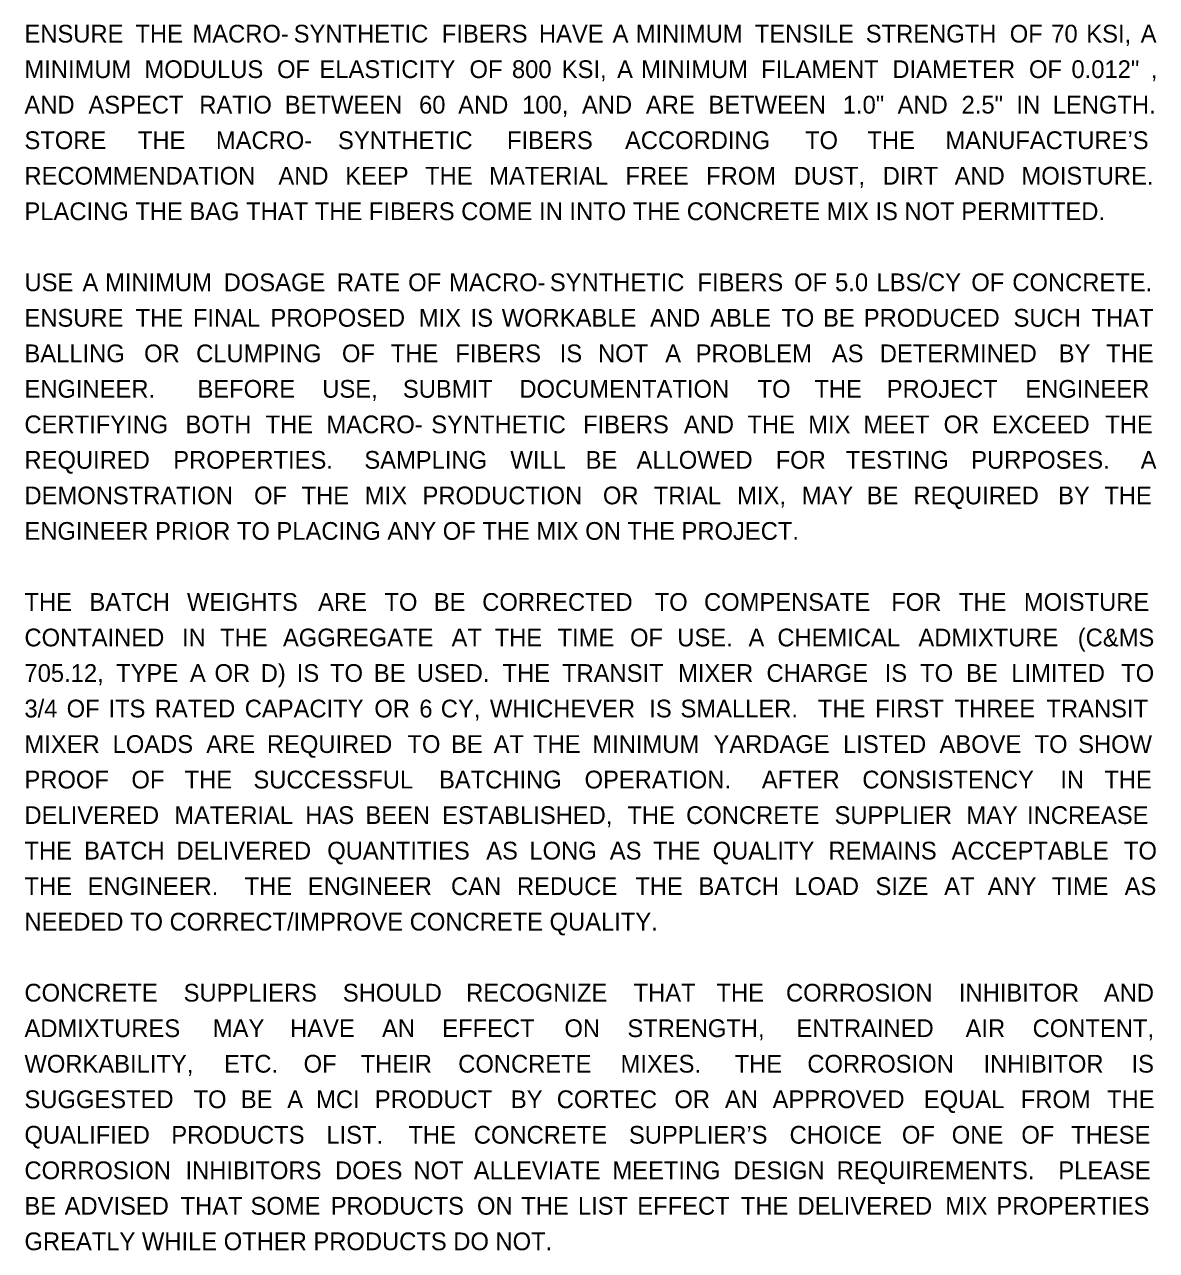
# Model space of a CAD drawing. Extents: x -19.8 to 34, y 0 to 22.
# Drawn here: x -19.82 to -10.9, y 1.96 to 11.62 of the extents above; entities that cross this region are included whole.
import ezdxf

# ---------------------------------------------------------------- set-up
doc = ezdxf.new("R2010")
doc.units = 0
doc.layers.add('SH_Text', color=7, linetype='Continuous')

msp = doc.modelspace()

# ---------------------------------------------------------------- texts
at = {"layer": 'SH_Text'}
for s, p in [('ENSURE ', (-19.8201, 11.48)), ('THE ', (-18.9457, 11.48)), ('MACRO-', (-18.4954, 11.48)), ('SYNTHETIC ', (-17.6975, 11.48)), ('FIBERS ', (-16.5298, 11.48)), ('HAVE ', (-15.7642, 11.48)), ('A ', (-15.1832, 11.48)), ('MINIMUM ', (-15.0009, 11.48)), ('TENSILE ', (-14.0619, 11.48)), ('STRENGTH ', (-13.1875, 11.48)), ('OF ', (-12.0525, 11.48)), ('70 ', (-11.7253, 11.48)), ('KSI, ', (-11.4489, 11.48)), ('A ', (-11.0202, 11.48)), ('MINIMUM ', (-19.8201, 11.2)), ('MODULUS ', (-18.8736, 11.2)), ('OF ', (-17.8289, 11.2)), ('ELASTICITY ', (-17.4943, 11.2)), ('OF ', (-16.3116, 11.2)), ('800 ', (-15.977, 11.2)), ('KSI, ', (-15.5843, 11.2)), ('A ', (-15.1482, 11.2)), ('MINIMUM ', (-14.9584, 11.2)), ('FILAMENT ', (-14.0119, 11.2)), ('DIAMETER ', (-12.9781, 11.2)), ('OF ', (-11.9008, 11.2)), ('0.012" ', (-11.5661, 11.2)), (', ', (-10.9409, 11.2)), ('AND ', (-19.8201, 10.92)), ('ASPECT ', (-19.3159, 10.92)), ('RATIO ', (-18.4421, 10.92)), ('BETWEEN ', (-17.7677, 10.92)), ('60 ', (-16.7092, 10.92)), ('AND ', (-16.4007, 10.92)), ('100, ', (-15.8965, 10.92)), ('AND ', (-15.4249, 10.92)), ('ARE ', (-14.9208, 10.92)), ('BETWEEN ', (-14.4274, 10.92)), ('1.0" ', (-13.3689, 10.92)), ('AND ', (-12.9366, 10.92)), ('2.5" ', (-12.4324, 10.92)), ('IN ', (-12.0001, 10.92)), ('LENGTH.  ', (-11.7134, 10.92)), ('STORE ', (-19.8201, 10.64)), ('THE ', (-18.926, 10.64)), ('MACRO-', (-18.311, 10.64)), ('SYNTHETIC ', (-17.3484, 10.64)), ('FIBERS ', (-16.016, 10.64)), ('ACCORDING ', (-15.0857, 10.64)), ('TO ', (-13.6665, 10.64)), ('THE ', (-13.1747, 10.64)), ('MANUFACTURE’S ', (-12.5597, 10.64)), ('RECOMMENDATION ', (-19.8201, 10.36)), ('AND ', (-17.8183, 10.36)), ('KEEP ', (-17.291, 10.36)), ('THE ', (-16.6619, 10.36)), ('MATERIAL ', (-16.1563, 10.36)), ('FREE ', (-15.0817, 10.36)), ('FROM ', (-14.4456, 10.36)), ('DUST, ', (-13.7554, 10.36)), ('DIRT ', (-13.0542, 10.36)), ('AND ', (-12.487, 10.36)), ('MOISTURE.  ', (-11.9597, 10.36)), ('PLACING THE BAG THAT THE FIBERS COME IN INTO THE CONCRETE MIX IS NOT PERMITTED.', (-19.8201, 10.08)), ('LBS/CY ', (-13.1027, 9.52)), ('USE ', (-19.8201, 9.52)), ('A ', (-19.3628, 9.52)), ('MINIMUM ', (-19.1845, 9.52)), ('DOSAGE ', (-18.2495, 9.52)), ('RATE ', (-17.3574, 9.52)), ('OF ', (-16.7951, 9.52)), ('MACRO-', (-16.4719, 9.52)), ('SYNTHETIC ', (-15.678, 9.52)), ('FIBERS ', (-14.5143, 9.52)), ('OF ', (-13.7527, 9.52)), ('5.0 ', (-13.4295, 9.52)), ('OF ', (-12.3554, 9.52)), ('CONCRETE.  ', (-12.0322, 9.52)), ('ENSURE ', (-19.8201, 9.24)), ('THE ', (-18.9441, 9.24)), ('FINAL ', (-18.4922, 9.24)), ('PROPOSED ', (-17.8808, 9.24)), ('MIX ', (-16.7112, 9.24)), ('IS ', (-16.3029, 9.24)), ('WORKABLE ', (-16.0574, 9.24)), ('AND ', (-14.888, 9.24)), ('ABLE ', (-14.4143, 9.24)), ('TO ', (-13.8535, 9.24)), ('BE ', (-13.5247, 9.24)), ('PRODUCED ', (-13.203, 9.24)), ('SUCH ', (-12.0229, 9.24)), ('THAT ', (-11.4079, 9.24)), ('BALLING ', (-19.8201, 8.96)), ('OR ', (-18.8769, 8.96)), ('CLUMPING ', (-18.4666, 8.96)), ('OF ', (-17.3172, 8.96)), ('THE ', (-16.9321, 8.96)), ('FIBERS ', (-16.4239, 8.96)), ('IS ', (-15.6004, 8.96)), ('NOT ', (-15.2986, 8.96)), ('A ', (-14.7688, 8.96)), ('PROBLEM ', (-14.5286, 8.96)), ('AS ', (-13.4551, 8.96)), ('DETERMINED ', (-13.0771, 8.96)), ('BY ', (-11.6668, 8.96)), ('THE ', (-11.2924, 8.96)), ('ENGINEER.   ', (-19.8201, 8.68)), ('BEFORE ', (-18.4561, 8.68)), ('USE, ', (-17.4725, 8.68)), ('SUBMIT ', (-16.8367, 8.68)), ('DOCUMENTATION ', (-15.9184, 8.68)), ('TO ', (-14.0402, 8.68)), ('THE ', (-13.5929, 8.68)), ('PROJECT ', (-13.0224, 8.68)), ('ENGINEER ', (-11.9301, 8.68)), ('CERTIFYING ', (-19.8201, 8.4)), ('BOTH ', (-18.5509, 8.4)), ('THE ', (-17.9194, 8.4)), ('MACRO-', (-17.44, 8.4)), ('SYNTHETIC ', (-16.613, 8.4)), ('FIBERS ', (-15.4163, 8.4)), ('AND ', (-14.6216, 8.4)), ('THE ', (-14.1205, 8.4)), ('MIX ', (-13.6411, 8.4)), ('MEET ', (-13.2053, 8.4)), ('OR ', (-12.5738, 8.4)), ('EXCEED ', (-12.1923, 8.4)), ('THE ', (-11.2997, 8.4)), ('REQUIRED ', (-19.8201, 8.12)), ('PROPERTIES.  ', (-18.6471, 8.12)), ('SAMPLING ', (-17.1406, 8.12)), ('WILL ', (-15.9893, 8.12)), ('BE ', (-15.3961, 8.12)), ('ALLOWED ', (-14.9948, 8.12)), ('FOR ', (-13.8979, 8.12)), ('TESTING ', (-13.3446, 8.12)), ('PURPOSES.  ', (-12.3564, 8.12)), ('A ', (-11.0202, 8.12)), ('DEMONSTRATION ', (-19.8201, 7.84)), ('OF ', (-18.0103, 7.84)), ('THE ', (-17.6351, 7.84)), ('MIX ', (-17.1367, 7.84)), ('PRODUCTION ', (-16.6819, 7.84)), ('OR ', (-15.2598, 7.84)), ('TRIAL ', (-14.8592, 7.84)), ('MIX, ', (-14.2014, 7.84)), ('MAY ', (-13.6922, 7.84)), ('BE ', (-13.1792, 7.84)), ('REQUIRED ', (-12.8112, 7.84)), ('BY ', (-11.6715, 7.84)), ('THE ', (-11.3069, 7.84)), ('ENGINEER PRIOR TO PLACING ANY OF THE MIX ON THE PROJECT.  ', (-19.8201, 7.56)), ('THE ', (-19.8201, 7)), ('BATCH ', (-19.308, 7)), ('WEIGHTS ', (-18.5387, 7)), ('ARE ', (-17.5051, 7)), ('TO ', (-16.982, 7)), ('BE ', (-16.5931, 7)), ('CORRECTED ', (-16.2114, 7)), ('TO ', (-14.8515, 7)), ('COMPENSATE ', (-14.4626, 7)), ('FOR ', (-12.9867, 7)), ('THE ', (-12.4529, 7)), ('MOISTURE ', (-11.9409, 7)), ('CONTAINED ', (-19.8201, 6.72)), ('AGGREGATE ', (-17.7823, 6.72)), ('OF ', (-15.0458, 6.72)), ('USE. ', (-14.6732, 6.72)), ('CHEMICAL ', (-13.8845, 6.72)), ('(C&MS ', (-11.5162, 6.72)), ('IN ', (-18.5781, 6.72)), ('THE ', (-18.278, 6.72)), ('AT ', (-16.4531, 6.72)), ('THE ', (-16.1132, 6.72)), ('TIME ', (-15.6175, 6.72)), ('A ', (-14.1122, 6.72)), ('ADMIXTURE ', (-12.7727, 6.72)), ('705.12, ', (-19.8201, 6.44)), ('TYPE ', (-19.0972, 6.44)), ('A ', (-18.5157, 6.44)), ('OR ', (-18.3218, 6.44)), ('D) ', (-17.9578, 6.44)), ('IS ', (-17.6738, 6.44)), ('TO ', (-17.4113, 6.44)), ('BE ', (-17.0655, 6.44)), ('USED. ', (-16.7268, 6.44)), ('THE ', (-16.0512, 6.44)), ('TRANSIT ', (-15.5822, 6.44)), ('MIXER ', (-14.6677, 6.44)), ('CHARGE ', (-13.9704, 6.44)), ('IS ', (-13.0386, 6.44)), ('TO ', (-12.759, 6.44)), ('BE ', (-12.3961, 6.44)), ('LIMITED ', (-12.0403, 6.44)), ('TO ', (-11.1739, 6.44)), ('3/4 ', (-19.8201, 6.16)), ('OF ', (-19.4873, 6.16)), ('ITS ', (-19.1582, 6.16)), ('RATED ', (-18.7928, 6.16)), ('CAPACITY ', (-18.0833, 6.16)), ('OR ', (-17.0619, 6.16)), ('6 ', (-16.7075, 6.16)), ('CY, ', (-16.5378, 6.16)), ('WHICHEVER ', (-16.1507, 6.16)), ('IS ', (-14.8941, 6.16)), ('SMALLER.  ', (-14.6483, 6.16)), ('THE ', (-13.5655, 6.16)), ('FIRST ', (-13.1132, 6.16)), ('THREE ', (-12.4871, 6.16)), ('TRANSIT ', (-11.763, 6.16)), ('MIXER ', (-19.8201, 5.88)), ('LOADS ', (-19.1252, 5.88)), ('ARE ', (-18.3866, 5.88)), ('REQUIRED ', (-17.9089, 5.88)), ('TO ', (-16.8009, 5.88)), ('BE ', (-16.4573, 5.88)), ('AT ', (-16.1209, 5.88)), ('THE ', (-15.81, 5.88)), ('MINIMUM ', (-15.3433, 5.88)), ('YARDAGE ', (-14.3879, 5.88)), ('LISTED ', (-13.3666, 5.88)), ('ABOVE ', (-12.6063, 5.88)), ('TO ', (-11.8568, 5.88)), ('SHOW ', (-11.5132, 5.88)), ('PROOF ', (-19.8201, 5.6)), ('OF ', (-18.9768, 5.6)), ('THE ', (-18.5575, 5.6)), ('SUCCESSFUL ', (-18.015, 5.6)), ('BATCHING ', (-16.552, 5.6)), ('OPERATION.  ', (-15.4045, 5.6)), ('AFTER ', (-14.007, 5.6)), ('CONSISTENCY ', (-13.2145, 5.6)), ('IN ', (-11.6537, 5.6)), ('THE ', (-11.3069, 5.6)), ('DELIVERED ', (-19.8201, 5.32)), ('MATERIAL ', (-18.639, 5.32)), ('HAS ', (-17.6066, 5.32)), ('BEEN ', (-17.1322, 5.32)), ('ESTABLISHED, ', (-16.5272, 5.32)), ('THE ', (-15.0671, 5.32)), ('CONCRETE ', (-14.6036, 5.32)), ('SUPPLIER ', (-13.4337, 5.32)), ('MAY ', (-12.3939, 5.32)), ('INCREASE ', (-11.9158, 5.32)), ('THE ', (-19.8201, 5.04)), ('BATCH ', (-19.3494, 5.04)), ('DELIVERED ', (-18.6214, 5.04)), ('QUANTITIES ', (-17.4331, 5.04)), ('AS ', (-16.1798, 5.04)), ('LONG ', (-15.8394, 5.04)), ('AS ', (-15.2056, 5.04)), ('THE ', (-14.8652, 5.04)), ('QUALITY ', (-14.3945, 5.04)), ('REMAINS ', (-13.4816, 5.04)), ('ACCEPTABLE ', (-12.5108, 5.04)), ('TO ', (-11.1521, 5.04)), ('THE ', (-19.8201, 4.76)), ('ENGINEER.  ', (-19.3219, 4.76)), ('THE ', (-18.0845, 4.76)), ('ENGINEER ', (-17.5862, 4.76)), ('CAN ', (-16.4575, 4.76)), ('REDUCE ', (-15.9374, 4.76)), ('THE ', (-15.0044, 4.76)), ('BATCH ', (-14.5061, 4.76)), ('LOAD ', (-13.7506, 4.76)), ('SIZE ', (-13.111, 4.76)), ('AT ', (-12.5692, 4.76)), ('ANY ', (-12.2268, 4.76)), ('TIME ', (-11.7211, 4.76)), ('AS ', (-11.1469, 4.76)), ('NEEDED TO CORRECT/IMPROVE CONCRETE QUALITY.', (-19.8201, 4.48)), ('CONCRETE ', (-19.8201, 3.92)), ('SUPPLIERS ', (-18.5653, 3.92)), ('SHOULD ', (-17.3102, 3.92)), ('RECOGNIZE ', (-16.338, 3.92)), ('THAT ', (-15.018, 3.92)), ('THE ', (-14.3647, 3.92)), ('CORROSION ', (-13.8164, 3.92)), ('INHIBITOR ', (-12.453, 3.92)), ('AND ', (-11.3106, 3.92)), ('ADMIXTURES ', (-19.8201, 3.64)), ('MAY ', (-18.3347, 3.64)), ('HAVE ', (-17.7261, 3.64)), ('AN ', (-17.0013, 3.64)), ('EFFECT ', (-16.5268, 3.64)), ('ON ', (-15.5633, 3.64)), ('STRENGTH, ', (-15.0671, 3.64)), ('ENTRAINED ', (-13.734, 3.64)), ('AIR ', (-12.4008, 3.64)), ('CONTENT, ', (-11.872, 3.64)), ('WORKABILITY, ', (-19.8201, 3.36)), ('ETC. ', (-18.2469, 3.36)), ('OF ', (-17.6194, 3.36)), ('THEIR ', (-17.1693, 3.36)), ('CONCRETE ', (-16.4005, 3.36)), ('MIXES.  ', (-15.1207, 3.36)), ('THE ', (-14.2214, 3.36)), ('CORROSION ', (-13.6482, 3.36)), ('INHIBITOR ', (-12.2598, 3.36)), ('IS ', (-11.0925, 3.36)), ('SUGGESTED ', (-19.8201, 3.08)), ('TO ', (-18.487, 3.08)), ('BE ', (-18.1143, 3.08)), ('A ', (-17.7486, 3.08)), ('MCI ', (-17.5207, 3.08)), ('PRODUCT ', (-17.0576, 3.08)), ('BY ', (-15.9856, 3.08)), ('CORTEC ', (-15.6235, 3.08)), ('OR ', (-14.6964, 3.08)), ('AN ', (-14.2983, 3.08)), ('APPROVED ', (-13.9219, 3.08)), ('EQUAL ', (-12.73, 3.08)), ('FROM ', (-11.9657, 3.08)), ('THE ', (-11.2852, 3.08)), ('QUALIFIED ', (-19.8201, 2.8)), ('PRODUCTS ', (-18.6627, 2.8)), ('LIST.  ', (-17.44, 2.8)), ('THE ', (-16.7935, 2.8)), ('CONCRETE ', (-16.2774, 2.8)), ('SUPPLIER’S ', (-15.0547, 2.8)), ('CHOICE ', (-13.7884, 2.8)), ('OF ', (-12.9027, 2.8)), ('ONE ', (-12.5097, 2.8)), ('OF ', (-11.9609, 2.8)), ('THESE ', (-11.5679, 2.8)), ('CORROSION ', (-19.8201, 2.52)), ('INHIBITORS ', (-18.5505, 2.52)), ('DOES ', (-17.3714, 2.52)), ('NOT ', (-16.7537, 2.52)), ('ALLEVIATE ', (-16.2776, 2.52)), ('MEETING ', (-15.1851, 2.52)), ('DESIGN ', (-14.2307, 2.52)), ('REQUIREMENTS.  ', (-13.4175, 2.52)), ('PLEASE ', (-11.6696, 2.52)), ('BE ', (-19.8201, 2.24)), ('ADVISED ', (-19.5036, 2.24)), ('THAT ', (-18.5893, 2.24)), ('SOME ', (-18.0375, 2.24)), ('PRODUCTS ', (-17.406, 2.24)), ('ON ', (-16.2527, 2.24)), ('THE ', (-15.9038, 2.24)), ('LIST ', (-15.4571, 2.24)), ('EFFECT ', (-14.9885, 2.24)), ('THE ', (-14.1723, 2.24)), ('DELIVERED ', (-13.7255, 2.24)), ('MIX ', (-12.5611, 2.24)), ('PROPERTIES ', (-12.1579, 2.24)), ('GREATLY WHILE OTHER PRODUCTS DO NOT.', (-19.8201, 1.96))]:
    msp.add_text(s, height=0.14, dxfattribs=at).set_placement(p)

doc.saveas('drawing.dxf')
